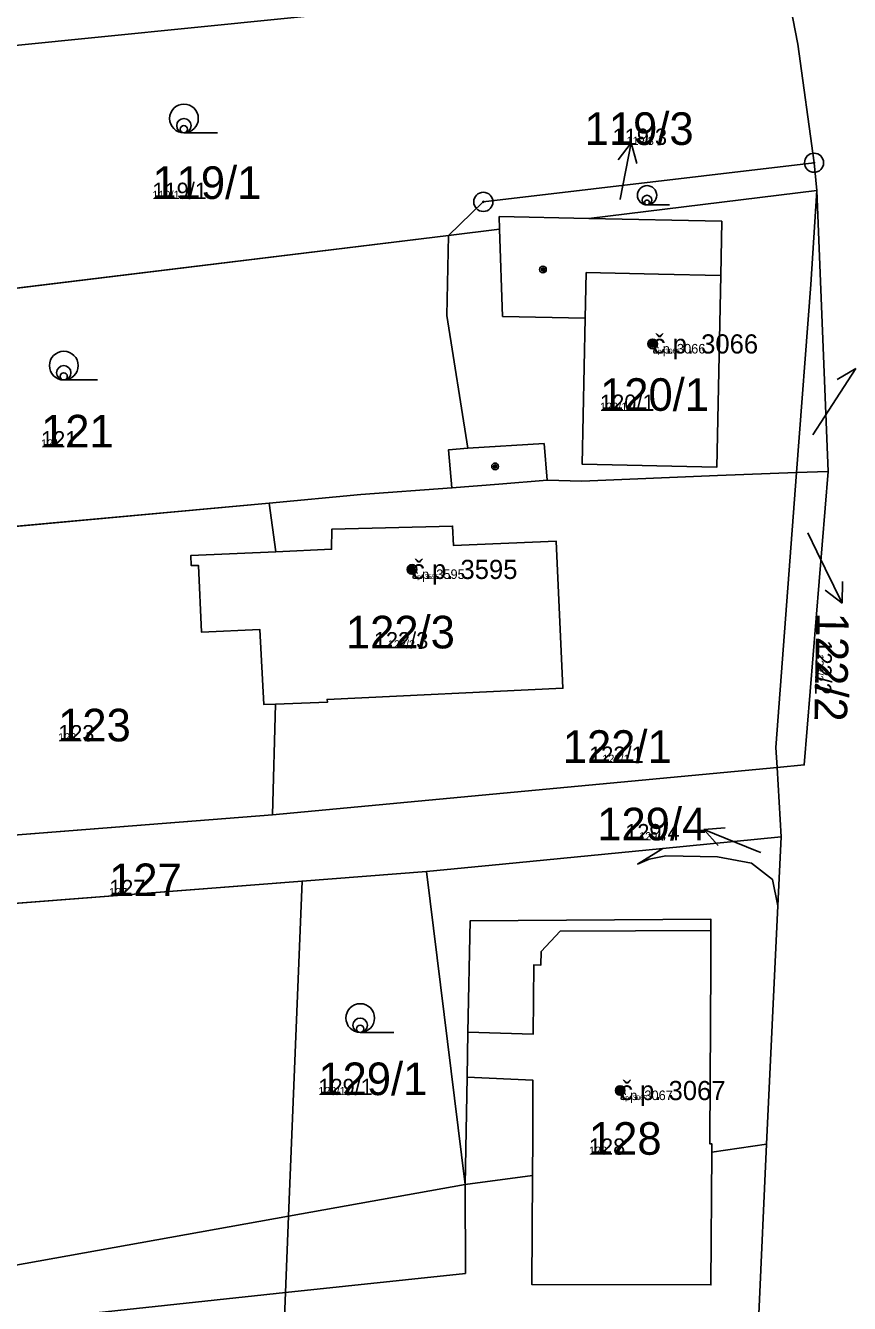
# Model space of a CAD drawing. Extents: x -759873 to -758487, y -975024 to -973516.
# Drawn here: x -759340.9 to -759297.9, y -974403.4 to -974336.8 of the extents above; entities that cross this region are included whole.
import ezdxf

# ---------------------------------------------------------------- set-up
doc = ezdxf.new("R2010")
doc.units = 0
for name, color, linetype in [('KAT_02_hranice parcel', 7, 'Continuous'), ('KAT_03_1000_st čísla parcelní', 7, 'Continuous'), ('KAT_03_1000_čísla parcelní', 7, 'Continuous'), ('KAT_03_1000_čísla popisná', 7, 'Continuous'), ('KAT_03_250_st čísla parcelní', 7, 'Continuous'), ('KAT_03_250_čísla parcelní', 7, 'Continuous'), ('KAT_03_250_čísla popisná', 7, 'Continuous'), ('KAT_03_500_st čísla parcelní', 7, 'Continuous'), ('KAT_03_500_čísla parcelní', 7, 'Continuous'), ('KAT_03_500_čísla popisná', 7, 'Continuous'), ('KAT_04_vnitřní kresba', 7, 'Continuous'), ('KAT_05_1000_značky kultur', 7, 'Continuous'), ('KAT_05_250_značky kultur', 7, 'Continuous'), ('KAT_05_500_značky kultur', 7, 'Continuous'), ('KAT_07_1000_značky budov', 7, 'Continuous'), ('KAT_07_250_značky budov', 7, 'Continuous'), ('KAT_07_500_značky budov', 7, 'Continuous'), ('KAT_11_značky bodu BP', 7, 'Continuous'), ('KAT_12_pomocná šipka', 7, 'Continuous'), ('KAT_14_plocha_budovy', 7, 'Continuous'), ('KAT_14_plocha_pozemek', 7, 'Continuous')]:
    doc.layers.add(name, color=color, linetype=linetype)

msp = doc.modelspace()

# ---------------------------------------------------------------- linework, layer by layer
at = {"layer": 'KAT_02_hranice parcel'}
for p, q in [((-759299.65, -974345.36), (-759299.79, -974343.91)), ((-759299.06, -974360.01), (-759299.65, -974345.36)), ((-759361.9, -974352.95), (-759318.86, -974347.71)), ((-759300.7, -974360.07), (-759299.06, -974360.01)), ((-759359.18, -974364.49), (-759328.22, -974361.67)), ((-759328.22, -974361.67), (-759327.87, -974364.2)), ((-759327.89, -974372.15), (-759328.05, -974377.92)), ((-759328.05, -974377.92), (-759301.72, -974375.45)), ((-759301.51, -974379.07), (-759301.72, -974375.45)), ((-759355.98, -974380.12), (-759328.05, -974377.92)), ((-759307.69, -974379.67), (-759301.51, -974379.07)), ((-759301.51, -974379.07), (-759301.68, -974382.67)), ((-759360.24, -974383.98), (-759326.51, -974381.38)), ((-759326.51, -974381.38), (-759327.22, -974398.86)), ((-759302.28, -974395.1), (-759301.68, -974382.67)), ((-759305.13, -974395.51), (-759302.28, -974395.1)), ((-759302.67, -974403.97), (-759302.28, -974395.1)), ((-759327.22, -974398.86), (-759318, -974397.2))]:
    msp.add_line(p, q, dxfattribs=at)
for points in [[(-759365.6, -974340.22), (-759303.52, -974333.97), (-759303.17, -974335.46), (-759301.15, -974335.03)], [(-759299.79, -974343.91), (-759300.63, -974337.72), (-759301.15, -974335.03)], [(-759318.86, -974347.71), (-759317.05, -974345.95), (-759299.79, -974343.91)], [(-759318.86, -974347.71), (-759316.2, -974347.38), (-759316.22, -974346.72), (-759311.55, -974346.82), (-759299.65, -974345.36)], [(-759300.7, -974360.07), (-759299.96, -974350.26), (-759299.65, -974345.36)], [(-759318.86, -974347.71), (-759318.95, -974351.87), (-759317.86, -974358.79), (-759318.86, -974358.88), (-759318.69, -974360.87)], [(-759318.69, -974360.87), (-759316.24, -974360.68), (-759313.71, -974360.46), (-759311.91, -974360.51), (-759304.83, -974360.23), (-759300.7, -974360.07)], [(-759301.72, -974375.45), (-759301.78, -974374.41), (-759300.7, -974360.07)], [(-759301.72, -974375.45), (-759300.3, -974375.32), (-759299.06, -974360.01)], [(-759328.22, -974361.67), (-759323.45, -974361.21), (-759318.69, -974360.87)], [(-759327.87, -974364.2), (-759324.97, -974364.07), (-759324.96, -974363.03), (-759318.65, -974362.86), (-759318.6, -974363.88), (-759313.24, -974363.65), (-759312.9, -974371.32), (-759325.2, -974371.9), (-759325.18, -974372.04), (-759327.89, -974372.15)], [(-759327.89, -974372.15), (-759328.5, -974372.17), (-759328.72, -974368.25), (-759331.76, -974368.39), (-759331.92, -974364.91), (-759332.29, -974364.92), (-759332.31, -974364.39), (-759327.87, -974364.2)], [(-759326.51, -974381.38), (-759320.01, -974380.88), (-759316.05, -974380.49), (-759307.69, -974379.67)], [(-759301.68, -974382.67), (-759301.96, -974381.29), (-759303.06, -974380.45), (-759304.83, -974380.11), (-759307.53, -974380.06), (-759308.39, -974380.24), (-759309, -974380.49), (-759307.69, -974379.67)], [(-759305.13, -974395.51), (-759305.13, -974395.08), (-759305.23, -974395.08), (-759305.23, -974394.85), (-759305.18, -974385.8), (-759305.17, -974383.96), (-759305.17, -974383.37), (-759317.74, -974383.45), (-759317.85, -974389.25), (-759317.89, -974391.61), (-759318, -974397.2)], [(-759318, -974397.2), (-759314.48, -974396.74), (-759314.51, -974402.42), (-759305.17, -974402.44), (-759305.13, -974395.51)], [(-759384.57, -974412.22), (-759381.52, -974408.61), (-759327.22, -974398.86)], [(-759327.22, -974398.86), (-759327.38, -974402.84), (-759327.97, -974417.54)]]:
    msp.add_lwpolyline(points, dxfattribs=at)
at = {"layer": 'KAT_03_1000_čísla popisná'}
for centre in [(-759308.21, -974353.36), (-759320.77, -974365.12), (-759309.91, -974392.3)]:
    msp.add_circle(centre, 0.25, dxfattribs=at)
at = {"layer": 'KAT_03_250_čísla popisná'}
for centre in [(-759308.21, -974353.36), (-759320.77, -974365.12), (-759309.91, -974392.3)]:
    msp.add_circle(centre, 0.0625, dxfattribs=at)
at = {"layer": 'KAT_03_500_čísla popisná'}
for centre in [(-759308.21, -974353.36), (-759320.77, -974365.12), (-759309.91, -974392.3)]:
    msp.add_circle(centre, 0.125, dxfattribs=at)
at = {"layer": 'KAT_04_vnitřní kresba'}
for p, q in [((-759304.6, -974346.96), (-759311.55, -974346.82)), ((-759304.6, -974346.96), (-759304.66, -974349.79)), ((-759316.2, -974347.38), (-759316.05, -974351.93)), ((-759311.73, -974352.02), (-759311.68, -974349.64)), ((-759311.68, -974349.64), (-759307.9, -974349.72)), ((-759307.9, -974349.72), (-759304.66, -974349.79)), ((-759304.87, -974359.79), (-759304.66, -974349.79)), ((-759311.73, -974352.02), (-759316.05, -974351.93)), ((-759311.89, -974359.64), (-759311.73, -974352.02)), ((-759317.86, -974358.79), (-759313.88, -974358.55)), ((-759313.88, -974358.55), (-759313.71, -974360.46)), ((-759311.89, -974359.64), (-759304.87, -974359.79)), ((-759320.01, -974380.88), (-759318, -974397.2)), ((-759313.04, -974383.99), (-759314.03, -974385.05)), ((-759305.17, -974383.96), (-759313.04, -974383.99)), ((-759314.03, -974385.05), (-759314.04, -974385.76)), ((-759314.42, -974385.75), (-759314.44, -974389.36)), ((-759314.04, -974385.76), (-759314.42, -974385.75)), ((-759317.85, -974389.25), (-759314.44, -974389.36)), ((-759314.46, -974391.76), (-759317.89, -974391.61)), ((-759314.46, -974391.76), (-759314.47, -974393.47)), ((-759314.47, -974393.47), (-759314.47, -974394.8)), ((-759314.48, -974396.74), (-759314.47, -974394.8)), ((-759318, -974397.2), (-759317.98, -974401.84)), ((-759327.38, -974402.84), (-759317.98, -974401.84)), ((-759381.52, -974408.61), (-759327.38, -974402.84))]:
    msp.add_line(p, q, dxfattribs=at)
at = {"layer": 'KAT_05_1000_značky kultur'}
for p, q in [((-759332.673, -974342.35), (-759330.923, -974342.35)), ((-759308.505, -974346.11), (-759307.333, -974346.11)), ((-759338.943, -974355.24), (-759337.193, -974355.24)), ((-759323.473, -974389.27), (-759321.723, -974389.27))]:
    msp.add_line(p, q, dxfattribs=at)
for centre, radius in [((-759332.673, -974341.6), 0.75), ((-759308.505, -974345.607), 0.502), ((-759338.943, -974354.49), 0.75), ((-759323.473, -974388.52), 0.75)]:
    msp.add_circle(centre, radius, dxfattribs=at)
at = {"layer": 'KAT_05_250_značky kultur'}
for p, q in [((-759332.678, -974342.35), (-759332.241, -974342.35)), ((-759308.509, -974346.11), (-759308.216, -974346.11)), ((-759338.948, -974355.24), (-759338.511, -974355.24)), ((-759323.478, -974389.27), (-759323.041, -974389.27))]:
    msp.add_line(p, q, dxfattribs=at)
for centre, radius in [((-759332.678, -974342.162), 0.187), ((-759308.509, -974345.984), 0.126), ((-759338.948, -974355.052), 0.187), ((-759323.478, -974389.082), 0.187)]:
    msp.add_circle(centre, radius, dxfattribs=at)
at = {"layer": 'KAT_05_500_značky kultur'}
for p, q in [((-759332.677, -974342.35), (-759331.802, -974342.35)), ((-759308.508, -974346.11), (-759307.922, -974346.11)), ((-759338.946, -974355.24), (-759338.071, -974355.24)), ((-759323.476, -974389.27), (-759322.601, -974389.27))]:
    msp.add_line(p, q, dxfattribs=at)
for centre, radius in [((-759332.676, -974341.975), 0.375), ((-759308.508, -974345.859), 0.251), ((-759338.946, -974354.865), 0.375), ((-759323.476, -974388.895), 0.375)]:
    msp.add_circle(centre, radius, dxfattribs=at)
at = {"layer": 'KAT_07_1000_značky budov'}
for centre in [(-759313.937, -974349.479), (-759308.217, -974353.359), (-759316.437, -974359.749), (-759320.777, -974365.119), (-759309.917, -974392.299)]:
    msp.add_circle(centre, 0.175, dxfattribs=at)
at = {"layer": 'KAT_07_250_značky budov'}
for centre in [(-759313.932, -974349.48), (-759308.212, -974353.36), (-759316.432, -974359.75), (-759320.772, -974365.12), (-759309.912, -974392.3)]:
    msp.add_circle(centre, 0.0437, dxfattribs=at)
at = {"layer": 'KAT_07_500_značky budov'}
for centre in [(-759313.933, -974349.48), (-759308.213, -974353.36), (-759316.433, -974359.75), (-759320.773, -974365.12), (-759309.913, -974392.3)]:
    msp.add_circle(centre, 0.0875, dxfattribs=at)
at = {"layer": 'KAT_11_značky bodu BP'}
for centre, radius in [((-759299.79, -974343.91), 0.5), ((-759299.79, -974343.91), 0.0303), ((-759317.05, -974345.95), 0.5), ((-759317.05, -974345.95), 0.0303)]:
    msp.add_circle(centre, radius, dxfattribs=at)
at = {"layer": 'KAT_12_pomocná šipka'}
for p, q in [((-759309.337, -974342.864), (-759310.02, -974343.752)), ((-759309.91, -974345.81), (-759309.337, -974342.864)), ((-759309.337, -974342.864), (-759309.037, -974343.943)), ((-759309.91, -974345.82), (-759309.91, -974345.81)), ((-759299.25, -974357.16), (-759297.616, -974354.643)), ((-759297.616, -974354.643), (-759298.581, -974355.21)), ((-759299.85, -974358.1), (-759299.25, -974357.16)), ((-759300.11, -974363.22), (-759299.64, -974364.18)), ((-759299.64, -974364.18), (-759298.324, -974366.877)), ((-759298.324, -974366.877), (-759299.214, -974366.197)), ((-759298.324, -974366.877), (-759298.313, -974365.758)), ((-759305.542, -974378.686), (-759304.426, -974378.597)), ((-759302.76, -974379.81), (-759305.542, -974378.686)), ((-759305.542, -974378.686), (-759304.802, -974379.525)), ((-759302.56, -974379.89), (-759302.76, -974379.81))]:
    msp.add_line(p, q, dxfattribs=at)
at = {"layer": 'KAT_14_plocha_budovy'}
for points in [[(-759311.73, -974352.02), (-759311.89, -974359.64), (-759304.87, -974359.79), (-759304.66, -974349.79), (-759307.9, -974349.72), (-759311.68, -974349.64)], [(-759327.87, -974364.2), (-759332.31, -974364.39), (-759332.29, -974364.92), (-759331.92, -974364.91), (-759331.76, -974368.39), (-759328.72, -974368.25), (-759328.5, -974372.17), (-759327.89, -974372.15), (-759325.18, -974372.04), (-759325.2, -974371.9), (-759312.9, -974371.32), (-759313.24, -974363.65), (-759318.6, -974363.88), (-759318.65, -974362.86), (-759324.96, -974363.03), (-759324.97, -974364.07)], [(-759314.51, -974402.42), (-759305.17, -974402.44), (-759305.13, -974395.51), (-759305.13, -974395.08), (-759305.23, -974395.08), (-759305.23, -974394.85), (-759305.18, -974385.8), (-759305.17, -974383.96), (-759313.04, -974383.99), (-759314.03, -974385.05), (-759314.04, -974385.76), (-759314.42, -974385.75), (-759314.44, -974389.36), (-759317.85, -974389.25), (-759317.89, -974391.61), (-759314.46, -974391.76), (-759314.47, -974393.47), (-759314.47, -974394.8), (-759314.48, -974396.74)]]:
    msp.add_lwpolyline(points, close=True, dxfattribs=at)
at = {"layer": 'KAT_14_plocha_pozemek'}
for points in [[(-759301.15, -974335.03), (-759301.4, -974333.76), (-759302.32, -974328.54), (-759303.06, -974322.52), (-759315.36, -974324.65), (-759319.42, -974322.54), (-759327.83, -974315.63), (-759333.29, -974309.02), (-759334.26, -974309.56), (-759341.8, -974312.79), (-759370.55, -974325.1), (-759365.6, -974340.22), (-759303.52, -974333.97), (-759303.17, -974335.46)], [(-759300.63, -974337.72), (-759301.15, -974335.03), (-759303.17, -974335.46), (-759303.52, -974333.97), (-759365.6, -974340.22), (-759364.94, -974342.25), (-759361.9, -974352.95), (-759318.86, -974347.71), (-759317.05, -974345.95), (-759299.79, -974343.91)], [(-759316.2, -974347.38), (-759316.22, -974346.72), (-759311.55, -974346.82), (-759299.65, -974345.36), (-759299.79, -974343.91), (-759317.05, -974345.95), (-759318.86, -974347.71)], [(-759299.65, -974345.36), (-759311.55, -974346.82), (-759316.22, -974346.72), (-759316.2, -974347.38), (-759318.86, -974347.71), (-759318.95, -974351.87), (-759317.86, -974358.79), (-759318.86, -974358.88), (-759318.69, -974360.87), (-759316.24, -974360.68), (-759313.71, -974360.46), (-759311.91, -974360.51), (-759304.83, -974360.23), (-759300.7, -974360.07), (-759299.96, -974350.26)], [(-759299.06, -974360.01), (-759299.65, -974345.36), (-759299.96, -974350.26), (-759300.7, -974360.07)], [(-759323.45, -974361.21), (-759318.69, -974360.87), (-759318.86, -974358.88), (-759317.86, -974358.79), (-759318.95, -974351.87), (-759318.86, -974347.71), (-759361.9, -974352.95), (-759359.18, -974364.49), (-759328.22, -974361.67)], [(-759327.89, -974372.15), (-759328.05, -974377.92), (-759301.72, -974375.45), (-759301.78, -974374.41), (-759300.7, -974360.07), (-759304.83, -974360.23), (-759311.91, -974360.51), (-759313.71, -974360.46), (-759316.24, -974360.68), (-759318.69, -974360.87), (-759323.45, -974361.21), (-759328.22, -974361.67), (-759327.87, -974364.2), (-759324.97, -974364.07), (-759324.96, -974363.03), (-759318.65, -974362.86), (-759318.6, -974363.88), (-759313.24, -974363.65), (-759312.9, -974371.32), (-759325.2, -974371.9), (-759325.18, -974372.04)], [(-759299.06, -974360.01), (-759300.7, -974360.07), (-759301.78, -974374.41), (-759301.72, -974375.45), (-759300.3, -974375.32)], [(-759328.5, -974372.17), (-759328.72, -974368.25), (-759331.76, -974368.39), (-759331.92, -974364.91), (-759332.29, -974364.92), (-759332.31, -974364.39), (-759327.87, -974364.2), (-759328.22, -974361.67), (-759359.18, -974364.49), (-759355.98, -974380.12), (-759328.05, -974377.92), (-759327.89, -974372.15)], [(-759327.89, -974372.15), (-759325.18, -974372.04), (-759325.2, -974371.9), (-759312.9, -974371.32), (-759313.24, -974363.65), (-759318.6, -974363.88), (-759318.65, -974362.86), (-759324.96, -974363.03), (-759324.97, -974364.07), (-759327.87, -974364.2), (-759332.31, -974364.39), (-759332.29, -974364.92), (-759331.92, -974364.91), (-759331.76, -974368.39), (-759328.72, -974368.25), (-759328.5, -974372.17)], [(-759301.51, -974379.07), (-759301.72, -974375.45), (-759328.05, -974377.92), (-759355.98, -974380.12), (-759360.8, -974380.25), (-759360.24, -974383.98), (-759326.51, -974381.38), (-759320.01, -974380.88), (-759316.05, -974380.49), (-759307.69, -974379.67)], [(-759307.69, -974379.67), (-759316.05, -974380.49), (-759320.01, -974380.88), (-759326.51, -974381.38), (-759327.22, -974398.86), (-759318, -974397.2), (-759317.89, -974391.61), (-759317.85, -974389.25), (-759317.74, -974383.45), (-759305.17, -974383.37), (-759305.17, -974383.96), (-759305.18, -974385.8), (-759305.23, -974394.85), (-759305.23, -974395.08), (-759305.13, -974395.08), (-759305.13, -974395.51), (-759302.28, -974395.1), (-759301.68, -974382.67), (-759301.96, -974381.29), (-759303.06, -974380.45), (-759304.83, -974380.11), (-759307.53, -974380.06), (-759308.39, -974380.24), (-759309, -974380.49)], [(-759307.69, -974379.67), (-759309, -974380.49), (-759308.39, -974380.24), (-759307.53, -974380.06), (-759304.83, -974380.11), (-759303.06, -974380.45), (-759301.96, -974381.29), (-759301.68, -974382.67), (-759301.51, -974379.07)], [(-759327.22, -974398.86), (-759326.51, -974381.38), (-759360.24, -974383.98), (-759369.6, -974385.4), (-759387.93, -974386.9), (-759390.61, -974387.43), (-759387.55, -974403.62), (-759384.57, -974412.22), (-759381.52, -974408.61)], [(-759305.17, -974383.37), (-759317.74, -974383.45), (-759317.85, -974389.25), (-759317.89, -974391.61), (-759318, -974397.2), (-759314.48, -974396.74), (-759314.51, -974402.42), (-759305.17, -974402.44), (-759305.13, -974395.51), (-759305.13, -974395.08), (-759305.23, -974395.08), (-759305.23, -974394.85), (-759305.18, -974385.8), (-759305.17, -974383.96)], [(-759302.28, -974395.1), (-759305.13, -974395.51), (-759305.17, -974402.44), (-759314.51, -974402.42), (-759314.48, -974396.74), (-759318, -974397.2), (-759327.22, -974398.86), (-759327.38, -974402.84), (-759327.97, -974417.54), (-759303.15, -974415.06), (-759302.67, -974403.97)], [(-759380.23, -974422.73), (-759327.97, -974417.54), (-759327.38, -974402.84), (-759327.22, -974398.86), (-759381.52, -974408.61), (-759384.57, -974412.22), (-759397.43, -974418.48), (-759395.04, -974424.2)]]:
    msp.add_lwpolyline(points, close=True, dxfattribs=at)
msp.add_lwpolyline([(-759301.15, -974335.03), (-759300.63, -974337.72), (-759299.79, -974343.91), (-759299.65, -974345.36), (-759299.06, -974360.01), (-759300.3, -974375.32), (-759301.72, -974375.45), (-759301.51, -974379.07), (-759301.68, -974382.67), (-759302.28, -974395.1), (-759302.67, -974403.97), (-759302.16, -974417.11), (-759301.82, -974428.21), (-759301.72, -974437.86), (-759302.31, -974447.39), (-759302.81, -974453.88)], dxfattribs=at)

# ---------------------------------------------------------------- texts
at = {"layer": 'KAT_03_1000_st čísla parcelní'}
for s, p in [('120/1', (-759310.96, -974356.85)), ('122/3', (-759324.223, -974369.24)), ('128', (-759311.54, -974395.65))]:
    msp.add_text(s, height=1.7, dxfattribs=at).set_placement(p)
at = {"layer": 'KAT_03_1000_čísla parcelní'}
for s, p in [('119/3', (-759311.763, -974342.98)), ('119/1', (-759334.32, -974345.799)), ('121', (-759340.13, -974358.76)), ('123', (-759339.24, -974374.09)), ('122/1', (-759312.903, -974375.21)), ('129/4', (-759311.103, -974379.25)), ('127', (-759336.58, -974382.16)), ('129/1', (-759325.66, -974392.539))]:
    msp.add_text(s, height=1.7, dxfattribs=at).set_placement(p)
msp.add_text('122/2', height=1.7, rotation=269, dxfattribs=at).set_placement((-759299.671, -974367.352))
at = {"layer": 'KAT_03_1000_čísla popisná'}
for s, p in [('č.p. 3066', (-759308.21, -974353.86)), ('č.p. 3595', (-759320.77, -974365.62)), ('č.p. 3067', (-759309.91, -974392.8))]:
    msp.add_text(s, height=1, dxfattribs=at).set_placement(p)
at = {"layer": 'KAT_03_250_st čísla parcelní'}
for s, p in [('120/1', (-759310.96, -974356.85)), ('122/3', (-759322.035, -974369.24)), ('128', (-759311.54, -974395.65))]:
    msp.add_text(s, height=0.425, dxfattribs=at).set_placement(p)
at = {"layer": 'KAT_03_250_čísla parcelní'}
for s, p in [('119/3', (-759309.575, -974342.98)), ('119/1', (-759334.32, -974345.799)), ('121', (-759340.13, -974358.76)), ('123', (-759339.24, -974374.09)), ('122/1', (-759310.839, -974375.21)), ('129/4', (-759308.918, -974379.25)), ('127', (-759336.58, -974382.16)), ('129/1', (-759325.66, -974392.539))]:
    msp.add_text(s, height=0.425, dxfattribs=at).set_placement(p)
msp.add_text('122/2', height=0.425, rotation=269, dxfattribs=at).set_placement((-759299.709, -974369.532))
at = {"layer": 'KAT_03_250_čísla popisná'}
for s, p in [('č.p. 3066', (-759308.21, -974353.86)), ('č.p. 3595', (-759320.77, -974365.62)), ('č.p. 3067', (-759309.91, -974392.8))]:
    msp.add_text(s, height=0.25, dxfattribs=at).set_placement(p)
at = {"layer": 'KAT_03_500_st čísla parcelní'}
for s, p in [('120/1', (-759310.96, -974356.85)), ('122/3', (-759322.765, -974369.24)), ('128', (-759311.54, -974395.65))]:
    msp.add_text(s, height=0.85, dxfattribs=at).set_placement(p)
at = {"layer": 'KAT_03_500_čísla parcelní'}
for s, p in [('119/3', (-759310.305, -974342.98)), ('119/1', (-759334.32, -974345.799)), ('121', (-759340.13, -974358.76)), ('123', (-759339.24, -974374.09)), ('122/1', (-759311.527, -974375.21)), ('129/4', (-759309.647, -974379.25)), ('127', (-759336.58, -974382.16)), ('129/1', (-759325.66, -974392.539))]:
    msp.add_text(s, height=0.85, dxfattribs=at).set_placement(p)
msp.add_text('122/2', height=0.85, rotation=269, dxfattribs=at).set_placement((-759299.696, -974368.806))
at = {"layer": 'KAT_03_500_čísla popisná'}
for s, p in [('č.p. 3066', (-759308.21, -974353.86)), ('č.p. 3595', (-759320.77, -974365.62)), ('č.p. 3067', (-759309.91, -974392.8))]:
    msp.add_text(s, height=0.5, dxfattribs=at).set_placement(p)

doc.saveas('drawing.dxf')
